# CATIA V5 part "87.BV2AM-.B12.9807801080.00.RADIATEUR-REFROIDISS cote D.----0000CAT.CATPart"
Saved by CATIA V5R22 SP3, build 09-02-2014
Part number: 9807801080
Revision: 000
Definition: RADIATEUR-REFROIDISS
Nomenclature: PIECE
Description: OCM
Bounding box of the stored display mesh (mm): x -732.668 to -632.46, y 328.743 to 399.507, z -1.861 to 498.931
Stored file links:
  C:\User\J535926\10-3D\En cours\P84\Cloisons antirecyclage\Envoi au fnr\150109\87.BV2AM-.B12.9807801080.00.RADIATEUR-REFROIDISS cote D.----0000CAT.CATPart
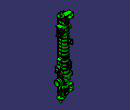
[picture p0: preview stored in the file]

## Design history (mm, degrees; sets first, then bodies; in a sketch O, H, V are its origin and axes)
Body1 (main body)
Body2 "OUTLET_TANK_210911\\MAIN TANK BODY"
  Solid1 "Solid.1": solid without history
